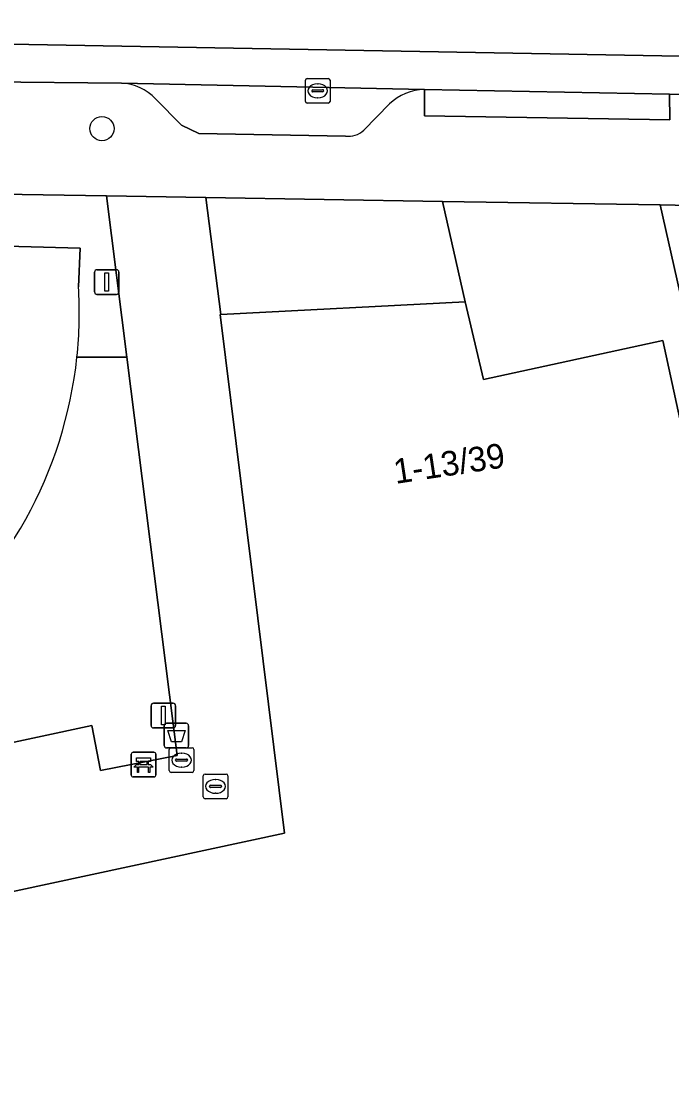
# Model space of a CAD drawing. Extents: x 163683 to 164494, y 382709 to 383872.
# Drawn here: x 164134.31 to 164160.65, y 383324.79 to 383367.98 of the extents above; entities that cross this region are included whole.
import ezdxf

# ---------------------------------------------------------------- set-up
doc = ezdxf.new("R2010")
doc.units = 0
for name, color, linetype in [('IMGEO_Afvalbak', 7, 'Continuous'), ('IMGEO_Bank', 7, 'Continuous'), ('IMGEO_Boom', 7, 'Continuous'), ('IMGEO_Groenvoorziening', 7, 'Continuous'), ('IMGEO_Kolk', 7, 'Continuous'), ('IMGEO_Lichtmast', 7, 'Continuous'), ('IMGEO_Pand', 7, 'Continuous'), ('IMGEO_Pand_nummerreeks', 7, 'Continuous'), ('IMGEO_Parkeervlak_open', 7, 'Continuous'), ('IMGEO_Rijbaan_lokaal_open', 7, 'Continuous'), ('IMGEO_Rioolput', 7, 'Continuous'), ('IMGEO_Voetpad_open', 7, 'Continuous')]:
    doc.layers.add(name, color=color, linetype=linetype)

msp = doc.modelspace()

# ---------------------------------------------------------------- linework, layer by layer
at = {"layer": 'IMGEO_Afvalbak'}
for p, q in [((164140.095, 383338.622), (164140.095, 383339.422)), ((164140.095, 383339.422), (164140.095, 383338.622)), ((164140.195, 383339.522), (164140.985, 383339.522)), ((164140.985, 383339.522), (164140.195, 383339.522)), ((164141.085, 383339.422), (164141.085, 383338.622)), ((164141.085, 383338.622), (164141.085, 383339.422)), ((164140.985, 383338.522), (164140.195, 383338.522)), ((164140.195, 383338.522), (164140.985, 383338.522))]:
    msp.add_line(p, q, dxfattribs=at)
msp.add_lwpolyline([(164140.238, 383339.236), (164140.942, 383339.236), (164140.793, 383338.766), (164140.387, 383338.766), (164140.238, 383339.236)], dxfattribs=at)
for centre, start, end in [((164140.195, 383339.422), 90, 180), ((164140.195, 383339.422), 90, 180), ((164140.985, 383339.422), 0, 90), ((164140.985, 383339.422), 360, 90), ((164140.195, 383338.622), 180, 270), ((164140.195, 383338.622), 180, 270), ((164140.985, 383338.622), 270, 0), ((164140.985, 383338.622), 270, 0)]:
    msp.add_arc(centre, 0.1, start, end, dxfattribs=at)
at = {"layer": 'IMGEO_Bank'}
for p, q in [((164138.761, 383337.424), (164138.761, 383338.265)), ((164138.761, 383338.265), (164138.761, 383337.424)), ((164138.836, 383338.349), (164139.677, 383338.349)), ((164139.677, 383338.349), (164138.836, 383338.349)), ((164139.761, 383338.274), (164139.761, 383337.433)), ((164139.761, 383337.433), (164139.761, 383338.274)), ((164139.458, 383337.747), (164139.065, 383337.747)), ((164139.07, 383337.855), (164139.07, 383337.961)), ((164139.114, 383337.961), (164139.114, 383337.855)), ((164139.402, 383337.967), (164139.12, 383337.967)), ((164139.12, 383337.849), (164139.402, 383337.849)), ((164139.408, 383337.855), (164139.408, 383337.961)), ((164139.452, 383337.961), (164139.452, 383337.855)), ((164139.686, 383337.349), (164138.845, 383337.349)), ((164138.845, 383337.349), (164139.686, 383337.349))]:
    msp.add_line(p, q, dxfattribs=at)
for points in [[(164139.064, 383337.967), (164138.978, 383337.967), (164138.978, 383338.128), (164139.541, 383338.128), (164139.541, 383337.967), (164139.458, 383337.967)], [(164139.008, 383337.747), (164138.866, 383337.747), (164138.978, 383337.849), (164139.064, 383337.849)], [(164139.058, 383337.74), (164139.058, 383337.533), (164139.015, 383337.533), (164139.015, 383337.74)], [(164139.458, 383337.849), (164139.541, 383337.849), (164139.653, 383337.747), (164139.514, 383337.747)], [(164139.508, 383337.74), (164139.508, 383337.533), (164139.464, 383337.533), (164139.464, 383337.74)]]:
    msp.add_lwpolyline(points, dxfattribs=at)
for centre, radius, start, end in [((164138.839, 383338.271), 0.0779, 92.4484, 184.2845), ((164138.839, 383338.271), 0.0779, 92.4484, 184.2845), ((164139.683, 383338.271), 0.0779, 2.4484, 94.2845), ((164139.683, 383338.271), 0.0779, 2.4484, 94.2845), ((164139.008, 383337.74), 0.00671, 2.8957, 87.1043), ((164139.065, 383337.74), 0.00671, 92.8957, 177.1043), ((164139.063, 383337.96), 0.00671, 2.8957, 87.1043), ((164139.063, 383337.856), 0.00671, 272.8957, 357.1043), ((164139.12, 383337.96), 0.00671, 92.8957, 177.1043), ((164139.12, 383337.856), 0.00671, 182.8957, 267.1043), ((164139.402, 383337.96), 0.00671, 2.8957, 87.1043), ((164139.402, 383337.856), 0.00671, 272.8957, 357.1043), ((164139.459, 383337.96), 0.00671, 92.8957, 177.1043), ((164139.459, 383337.856), 0.00671, 182.8957, 267.1043), ((164139.457, 383337.74), 0.00671, 2.8957, 87.1043), ((164139.514, 383337.74), 0.00671, 92.8957, 177.1043), ((164138.839, 383337.427), 0.0779, 182.4484, 274.2845), ((164138.839, 383337.427), 0.0779, 182.4484, 274.2845), ((164139.683, 383337.427), 0.0779, 272.4484, 4.2845), ((164139.683, 383337.427), 0.0779, 272.4484, 4.2845)]:
    msp.add_arc(centre, radius, start, end, dxfattribs=at)
at = {"layer": 'IMGEO_Boom'}
msp.add_circle((164137.573, 383363.626), 0.489, dxfattribs=at)
at = {"layer": 'IMGEO_Groenvoorziening'}
for points in [[(164136.561, 383354.363), (164138.583, 383354.363), (164137.756, 383360.901), (164131.761, 383361), (164131.713, 383358.915), (164136.688, 383358.786), (164136.624, 383357.219)], [(164121.101, 383339.915), (164122.679, 383334.36), (164130.931, 383336.11), (164130.549, 383338.008), (164137.17, 383339.433), (164137.516, 383337.615), (164140.626, 383338.214), (164138.583, 383354.363), (164136.561, 383354.363)]]:
    msp.add_lwpolyline(points, dxfattribs=at)
for points in [[(164151.37, 383360.677), (164141.778, 383360.835), (164142.394, 383356.096), (164152.282, 383356.605)], [(164119.156, 383296.39), (164121.819, 383296.004), (164122.79, 383307.57), (164171.2, 383318.018), (164162.016, 383360.502), (164160.187, 383360.532), (164165.055, 383338.875), (164165.344, 383338.944), (164167.451, 383329.183), (164165.973, 383328.818), (164167.864, 383320.086), (164121.192, 383310.032)]]:
    msp.add_lwpolyline(points, close=True, dxfattribs=at)
for centre, radius, start, end in [((164119.484, 383356.168), 17.172, 353.965, 3.5077), ((164119.411, 383356.171), 17.245, 307.9107, 353.9834)]:
    msp.add_arc(centre, radius, start, end, dxfattribs=at)
at = {"layer": 'IMGEO_Kolk'}
for p, q in [((164145.813, 383364.732), (164145.813, 383365.584)), ((164145.888, 383365.658), (164146.74, 383365.658)), ((164146.301, 383365.438), (164146.326, 383365.438)), ((164146.814, 383365.584), (164146.814, 383364.732)), ((164146.072, 383365.152), (164146.072, 383365.164)), ((164146.51, 383365.115), (164146.112, 383365.115)), ((164146.115, 383365.201), (164146.513, 383365.201)), ((164146.556, 383365.164), (164146.556, 383365.152)), ((164146.74, 383364.658), (164145.888, 383364.658)), ((164146.324, 383364.878), (164146.299, 383364.878))]:
    msp.add_line(p, q, dxfattribs=at)
for points in [[(164145.813, 383364.732), (164145.813, 383365.584)], [(164145.888, 383365.658), (164146.74, 383365.658)], [(164146.814, 383365.584), (164146.814, 383364.732)], [(164146.74, 383364.658), (164145.888, 383364.658)]]:
    msp.add_lwpolyline(points, dxfattribs=at)
for centre, radius, start, end in [((164145.89, 383365.582), 0.0765, 91.552, 178.448), ((164145.89, 383365.582), 0.0765, 91.552, 178.448), ((164146.738, 383365.582), 0.0765, 1.552, 88.448), ((164146.738, 383365.582), 0.0765, 1.552, 88.448), ((164146.112, 383365.161), 0.0403, 85.8775, 175.7526), ((164146.109, 383365.151), 0.0366, 178.938, 274.7102), ((164146.513, 383365.158), 0.043, 264.8664, 352.4533), ((164146.517, 383365.163), 0.0386, 1.7309, 96.639), ((164145.89, 383364.734), 0.0765, 181.552, 268.448), ((164145.89, 383364.734), 0.0765, 181.552, 268.448), ((164146.738, 383364.734), 0.0765, 271.552, 358.448), ((164146.738, 383364.734), 0.0765, 271.552, 358.448)]:
    msp.add_arc(centre, radius, start, end, dxfattribs=at)
for centre, major_axis, ratio, start_param, end_param in [((164146.3, 383365.158), (-0.387, 0.002), 0.722429, 4.712389, 7.853982), ((164146.325, 383365.158), (-0.39, 0.002), 0.717154, 1.570796, 4.712389)]:
    msp.add_ellipse(centre, major_axis=major_axis, ratio=ratio, start_param=start_param, end_param=end_param, dxfattribs=at)
at = {"layer": 'IMGEO_Lichtmast'}
for p, q in [((164137.273, 383357.006), (164137.273, 383357.806)), ((164137.273, 383357.806), (164137.273, 383357.006)), ((164137.373, 383357.906), (164138.163, 383357.906)), ((164138.163, 383357.906), (164137.373, 383357.906)), ((164138.263, 383357.806), (164138.263, 383357.006)), ((164138.263, 383357.006), (164138.263, 383357.806)), ((164138.163, 383356.906), (164137.373, 383356.906)), ((164137.373, 383356.906), (164138.163, 383356.906)), ((164139.665, 383340.336), (164140.455, 383340.336)), ((164140.455, 383340.336), (164139.665, 383340.336)), ((164139.565, 383339.436), (164139.565, 383340.236)), ((164139.565, 383340.236), (164139.565, 383339.436)), ((164140.555, 383340.236), (164140.555, 383339.436)), ((164140.555, 383339.436), (164140.555, 383340.236)), ((164140.455, 383339.336), (164139.665, 383339.336)), ((164139.665, 383339.336), (164140.455, 383339.336))]:
    msp.add_line(p, q, dxfattribs=at)
for points in [[(164137.693, 383357.781), (164137.843, 383357.781), (164137.843, 383357.031), (164137.693, 383357.031), (164137.693, 383357.781)], [(164139.985, 383340.211), (164140.135, 383340.211), (164140.135, 383339.461), (164139.985, 383339.461), (164139.985, 383340.211)]]:
    msp.add_lwpolyline(points, dxfattribs=at)
for centre, start, end in [((164137.373, 383357.806), 90, 180), ((164137.373, 383357.806), 90, 180), ((164138.163, 383357.806), 0, 90), ((164138.163, 383357.806), 360, 90), ((164137.373, 383357.006), 180, 270), ((164137.373, 383357.006), 180, 270), ((164138.163, 383357.006), 270, 0), ((164138.163, 383357.006), 270, 0), ((164139.665, 383340.236), 90, 180), ((164139.665, 383340.236), 90, 180), ((164140.455, 383340.236), 0, 90), ((164140.455, 383340.236), 360, 90), ((164139.665, 383339.436), 180, 270), ((164139.665, 383339.436), 180, 270), ((164140.455, 383339.436), 270, 0), ((164140.455, 383339.436), 270, 0)]:
    msp.add_arc(centre, 0.1, start, end, dxfattribs=at)
at = {"layer": 'IMGEO_Pand'}
msp.add_lwpolyline([(164165.905, 383329.135), (164160.295, 383355.04), (164153.023, 383353.46), (164152.282, 383356.605), (164142.394, 383356.096), (164142.367, 383356.094), (164144.967, 383335.071), (164108.893, 383327.316), (164107.919, 383314.448), (164103.954, 383315.494), (164100.092, 383316.499), (164099.232, 383316.726), (164085.894, 383320.243), (164081.08, 383302.369), (164083.28, 383301.798), (164087.253, 383300.767), (164106.517, 383295.769), (164105.106, 383276.669)], dxfattribs=at)
at = {"layer": 'IMGEO_Parkeervlak_open'}
for points in [[(164150.64, 383365.207), (164138.363, 383365.465)], [(164139.744, 383364.828), (164140.794, 383363.768)], [(164148.175, 383363.559), (164149.222, 383364.629)], [(164140.794, 383363.768), (164141.495, 383363.428)], [(164141.495, 383363.428), (164147.435, 383363.322)], [(164136.624, 383357.219), (164136.688, 383358.786), (164131.713, 383358.915)]]:
    msp.add_lwpolyline(points, dxfattribs=at)
for centre, radius, start, end in [((164138.291, 383363.493), 1.974, 42.5777, 87.8984), ((164150.662, 383363.124), 2.084, 90.617, 133.7362), ((164147.552, 383364.23), 0.916, 262.6553, 312.8621), ((164119.484, 383356.168), 17.172, 353.965, 3.5077), ((164119.411, 383356.171), 17.245, 307.9107, 353.9834)]:
    msp.add_arc(centre, radius, start, end, dxfattribs=at)
at = {"layer": 'IMGEO_Rijbaan_lokaal_open'}
for points in [[(164037.444, 383378.098), (164038.398, 383377.921), (164038.521, 383377.899), (164038.786, 383379.375), (164103.399, 383367.78), (164109.713, 383367.482), (164198.705, 383365.887), (164205.201, 383365.177), (164213.958, 383363.713), (164230.957, 383359.822), (164242.9, 383358.082), (164243.253, 383362.244), (164243.39, 383363.835), (164243.778, 383368.218)], [(164244.235, 383357.92), (164242.9, 383358.082), (164230.957, 383359.822), (164213.958, 383363.713), (164205.201, 383365.177), (164198.705, 383365.887), (164109.713, 383367.482), (164103.399, 383367.78), (164038.786, 383379.375)], [(164092.839, 383368.148), (164094.762, 383367.853), (164094.896, 383367.828), (164103.227, 383366.287), (164108.463, 383366.001), (164109.483, 383365.985), (164109.666, 383365.982), (164123.789, 383365.761), (164123.953, 383365.757), (164132.91, 383365.521), (164138.363, 383365.465), (164150.64, 383365.207), (164160.569, 383365.029), (164182.889, 383364.663), (164195.34, 383364.458), (164195.456, 383364.456), (164198.426, 383364.409), (164198.607, 383364.389), (164204.996, 383363.69), (164213.667, 383362.241), (164230.622, 383358.36), (164243.278, 383355.52)], [(164107.919, 383314.448), (164108.893, 383327.316), (164144.967, 383335.071), (164142.367, 383356.094), (164142.394, 383356.096), (164141.778, 383360.835), (164137.756, 383360.901), (164138.583, 383354.363), (164140.626, 383338.214), (164137.516, 383337.615), (164137.17, 383339.433), (164130.549, 383338.008), (164130.931, 383336.11), (164122.679, 383334.36), (164114.223, 383332.567), (164114.043, 383332.595), (164108.585, 383333.327)]]:
    msp.add_lwpolyline(points, dxfattribs=at)
at = {"layer": 'IMGEO_Rioolput'}
for p, q in [((164140.3, 383337.603), (164140.3, 383338.455)), ((164140.375, 383338.529), (164141.227, 383338.529)), ((164140.788, 383338.309), (164140.813, 383338.309)), ((164141.301, 383338.455), (164141.301, 383337.603)), ((164140.559, 383338.023), (164140.559, 383338.035)), ((164140.997, 383337.986), (164140.599, 383337.986)), ((164140.602, 383338.072), (164141, 383338.072)), ((164140.811, 383337.749), (164140.786, 383337.749)), ((164141.043, 383338.035), (164141.043, 383338.023)), ((164141.227, 383337.529), (164140.375, 383337.529)), ((164141.674, 383336.539), (164141.674, 383337.391)), ((164141.749, 383337.465), (164142.601, 383337.465)), ((164142.162, 383337.245), (164142.187, 383337.245)), ((164142.675, 383337.391), (164142.675, 383336.539)), ((164141.933, 383336.959), (164141.933, 383336.971)), ((164142.371, 383336.922), (164141.973, 383336.922)), ((164141.976, 383337.008), (164142.374, 383337.008)), ((164142.417, 383336.971), (164142.417, 383336.959)), ((164142.601, 383336.465), (164141.749, 383336.465)), ((164142.185, 383336.685), (164142.16, 383336.685))]:
    msp.add_line(p, q, dxfattribs=at)
for points in [[(164140.3, 383337.603), (164140.3, 383338.455)], [(164140.375, 383338.529), (164141.227, 383338.529)], [(164141.301, 383338.455), (164141.301, 383337.603)], [(164141.227, 383337.529), (164140.375, 383337.529)], [(164141.674, 383336.539), (164141.674, 383337.391)], [(164141.749, 383337.465), (164142.601, 383337.465)], [(164142.675, 383337.391), (164142.675, 383336.539)], [(164142.601, 383336.465), (164141.749, 383336.465)]]:
    msp.add_lwpolyline(points, dxfattribs=at)
for centre, radius, start, end in [((164140.377, 383338.453), 0.0765, 91.552, 178.448), ((164140.377, 383338.453), 0.0765, 91.552, 178.448), ((164141.225, 383338.453), 0.0765, 1.552, 88.448), ((164141.225, 383338.453), 0.0765, 1.552, 88.448), ((164140.599, 383338.032), 0.0403, 85.8775, 175.7526), ((164140.596, 383338.022), 0.0366, 178.938, 274.7102), ((164141, 383338.029), 0.043, 264.8664, 352.4533), ((164141.004, 383338.034), 0.0386, 1.7309, 96.639), ((164140.377, 383337.605), 0.0765, 181.552, 268.448), ((164140.377, 383337.605), 0.0765, 181.552, 268.448), ((164141.225, 383337.605), 0.0765, 271.552, 358.448), ((164141.225, 383337.605), 0.0765, 271.552, 358.448), ((164141.751, 383337.389), 0.0765, 91.552, 178.448), ((164141.751, 383337.389), 0.0765, 91.552, 178.448), ((164142.599, 383337.389), 0.0765, 1.552, 88.448), ((164142.599, 383337.389), 0.0765, 1.552, 88.448), ((164141.973, 383336.968), 0.0403, 85.8775, 175.7526), ((164141.97, 383336.958), 0.0366, 178.938, 274.7102), ((164142.374, 383336.965), 0.043, 264.8664, 352.4533), ((164142.378, 383336.97), 0.0386, 1.7309, 96.639), ((164141.751, 383336.541), 0.0765, 181.552, 268.448), ((164141.751, 383336.541), 0.0765, 181.552, 268.448), ((164142.599, 383336.541), 0.0765, 271.552, 358.448), ((164142.599, 383336.541), 0.0765, 271.552, 358.448)]:
    msp.add_arc(centre, radius, start, end, dxfattribs=at)
for centre, major_axis, ratio, start_param, end_param in [((164140.787, 383338.029), (-0.387, 0.002), 0.722429, 4.712389, 7.853982), ((164140.812, 383338.029), (-0.39, 0.002), 0.717154, 1.570796, 4.712389), ((164142.161, 383336.965), (-0.387, 0.002), 0.722429, 4.712389, 7.853982), ((164142.186, 383336.965), (-0.39, 0.002), 0.717154, 1.570796, 4.712389)]:
    msp.add_ellipse(centre, major_axis=major_axis, ratio=ratio, start_param=start_param, end_param=end_param, dxfattribs=at)
at = {"layer": 'IMGEO_Voetpad_open'}
for points in [[(164070.848, 383368.682), (164095.779, 383364.072), (164097.196, 383363.81), (164101.776, 383362.963), (164109.721, 383361.495), (164114.816, 383361.369), (164125.689, 383361.1), (164125.721, 383361.1), (164131.761, 383361), (164137.756, 383360.901), (164141.778, 383360.835), (164151.37, 383360.677), (164160.187, 383360.532), (164162.016, 383360.502), (164166.15, 383360.434), (164166.931, 383360.421), (164173.04, 383360.297), (164196.744, 383359.902), (164199.517, 383359.782), (164205.2, 383359.074), (164209.777, 383358.339), (164213.788, 383357.54), (164227.571, 383354.373)], [(164138.363, 383365.465), (164132.91, 383365.521), (164132.891, 383364.42), (164123.912, 383364.643), (164123.953, 383365.757), (164123.789, 383365.761)], [(164182.889, 383364.663), (164160.569, 383365.029), (164160.57, 383363.984), (164150.638, 383364.143), (164150.64, 383365.207)], [(164147.435, 383363.322), (164141.495, 383363.428), (164140.794, 383363.768), (164139.744, 383364.828)], [(164149.222, 383364.629), (164148.175, 383363.559)]]:
    msp.add_lwpolyline(points, dxfattribs=at)
for points in [[(164160.569, 383365.029), (164150.64, 383365.207), (164150.638, 383364.143), (164160.57, 383363.984)], [(164160.187, 383360.532), (164151.37, 383360.677), (164152.282, 383356.605), (164153.023, 383353.46), (164160.295, 383355.04), (164165.905, 383329.135), (164167.088, 383329.415), (164165.055, 383338.875)]]:
    msp.add_lwpolyline(points, close=True, dxfattribs=at)
for centre, radius, start, end in [((164138.291, 383363.493), 1.974, 42.5777, 87.8984), ((164150.662, 383363.124), 2.084, 90.617, 133.7362), ((164147.552, 383364.23), 0.916, 262.6553, 312.8621)]:
    msp.add_arc(centre, radius, start, end, dxfattribs=at)

# ---------------------------------------------------------------- texts
at = {"layer": 'IMGEO_Pand_nummerreeks'}
msp.add_text('1-13/39', height=1, rotation=8.6293, dxfattribs=at).set_placement((164149.468, 383349.224))

doc.saveas('drawing.dxf')
